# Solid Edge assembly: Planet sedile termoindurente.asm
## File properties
Title: Planet sedile termoindurente
Author: DESYS
Template: Normal.asm
Last saved by: s.pallini
Revision: 10
Application: Solid Edge
Tipo di contenuto documento: 1
Document Number: 8108/B
Revision: 0
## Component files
Planet sedile termoindurente-1.par
Planet sedile termoindurente-2.par
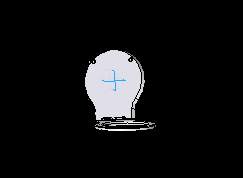
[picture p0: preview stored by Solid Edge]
